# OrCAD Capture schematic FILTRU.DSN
size A
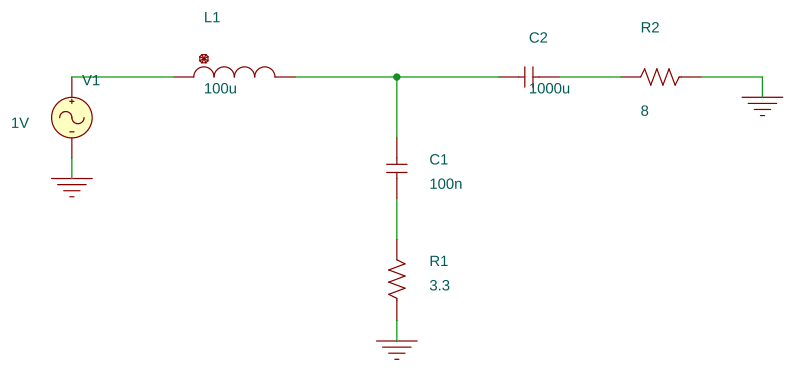
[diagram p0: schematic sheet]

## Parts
C1  100n  [cap196]
C2  1000u  [cap196]
L1  100u  [DISC350x175LS200x100034]
R1  3.3  [AXRC05]
R2  8  [AXRC05]
V1  VAC

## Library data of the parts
C1 C2 = C
L1 = L
R1 R2 = R
V1 = VAC: DC: 1V

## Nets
0: R1.1 R2.1 V1.2(-)
N00058: L1.1 V1.1(+)
N00113: C1.2 C2.1 L1.2
N00204: C2.2 R2.2
N00208: C1.1 R1.2
